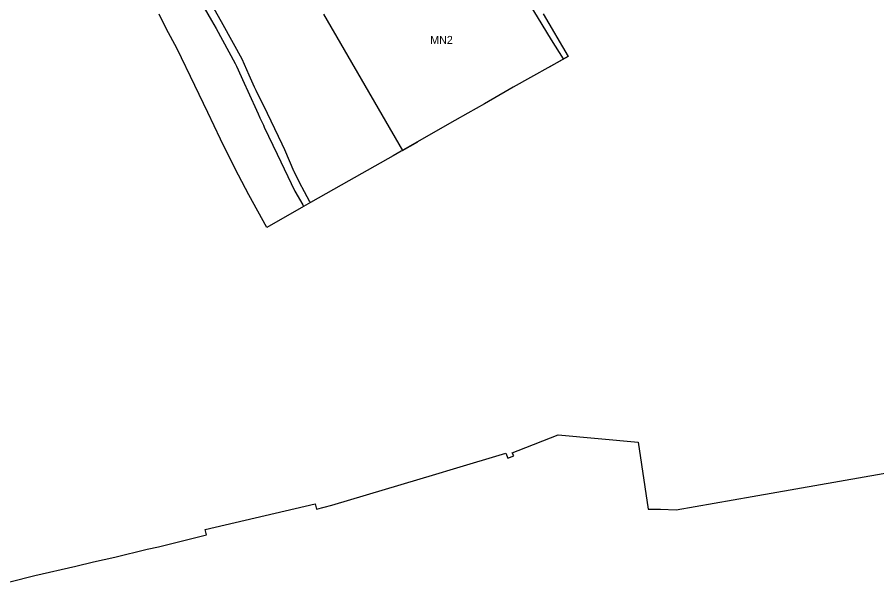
# Model space of a CAD drawing. Extents: x 7435758 to 7439981, y 5550649 to 5554049.
# Drawn here: x 7437513 to 7438071, y 5550874 to 5551241 of the extents above; entities that cross this region are included whole.
import ezdxf

# ---------------------------------------------------------------- set-up
doc = ezdxf.new("R2010")
doc.units = 0
for name, color, linetype in [('#Ruszcza', 7, 'Continuous'), ('linie_rozgraniczające', 7, 'Continuous'), ('linie_zabudowy_nieprzekraczalne', 7, 'Continuous'), ('oznaczenia_przeznaczen', 7, 'Continuous')]:
    doc.layers.add(name, color=color, linetype=linetype)

msp = doc.modelspace()

# ---------------------------------------------------------------- linework, layer by layer
at = {"layer": '#Ruszcza'}
for points in [[(7437854.67, 5551243.25), (7437871.03, 5551215.66), (7437835.33, 5551195.56), (7437832.76, 5551194.1), (7437816.62, 5551184.92), (7437805.84, 5551178.79), (7437797.36, 5551173.97), (7437781.8, 5551165.08), (7437762.51, 5551154.06), (7437757.35, 5551151.11), (7437728.49, 5551134.92), (7437703.62, 5551120.79), (7437699.13, 5551118.22), (7437675.21, 5551104.53), (7437663.51, 5551125.67), (7437656.96, 5551138.55), (7437649.87, 5551152.2), (7437645.25, 5551161.79), (7437636.88, 5551179.09), (7437628.45, 5551196.8), (7437617.02, 5551220.55), (7437609.91, 5551233.78), (7437605.33, 5551243.14)], [(7437508.31, 5550874.47), (7437524.48, 5550878.48), (7437551.28, 5550884.61), (7437562.64, 5550887.41), (7437576.65, 5550890.57), (7437597.53, 5550895.76), (7437604.87, 5550897.1), (7437619.64, 5550900.82), (7437636.09, 5550904.97), (7437635.19, 5550908.51), (7437706.77, 5550925.06), (7437707.57, 5550921.74), (7437717.56, 5550924.19), (7437785.08, 5550944.4), (7437796.47, 5550947.82), (7437830.56, 5550958.02), (7437831.89, 5550954.85), (7437835.66, 5550956.31), (7437834.56, 5550958.16), (7437838.51, 5550959.77), (7437864.51, 5550969.99), (7437916.46, 5550965.07), (7437922.95, 5550921.62), (7437930.91, 5550921.66), (7437941.14, 5550921.25), (7437990.62, 5550929.87), (7438103.91, 5550949.67)]]:
    msp.add_lwpolyline(points, dxfattribs=at)
at = {"layer": 'linie_rozgraniczające'}
for p, q in [((7437629.59, 5551255.8), (7437639.26, 5551239)), ((7437646.85, 5551236.19), (7437634.54, 5551258.52)), ((7437639.26, 5551239), (7437642.32, 5551233.68)), ((7437712.09, 5551243.15), (7437763.36, 5551154.58)), ((7437642.32, 5551233.68), (7437654.7, 5551211.03)), ((7437659.21, 5551213.76), (7437646.85, 5551236.19)), ((7437654.7, 5551211.03), (7437655.52, 5551209.24)), ((7437663.84, 5551203.45), (7437659.21, 5551213.76)), ((7437859.25, 5551209.03), (7437871, 5551215.7)), ((7437655.52, 5551209.24), (7437660.55, 5551198.16)), ((7437667.37, 5551195.62), (7437663.84, 5551203.45)), ((7437660.55, 5551198.16), (7437662.89, 5551193.01)), ((7437668.4, 5551193.49), (7437667.37, 5551195.62)), ((7437662.89, 5551193.01), (7437669.55, 5551178.39)), ((7437675.67, 5551178.51), (7437668.4, 5551193.49)), ((7437669.55, 5551178.39), (7437670.78, 5551175.69)), ((7437685.29, 5551158.53), (7437675.67, 5551178.51)), ((7437670.78, 5551175.69), (7437673.05, 5551170.95)), ((7437673.05, 5551170.95), (7437673.64, 5551169.71)), ((7437673.64, 5551169.71), (7437682.03, 5551152.21)), ((7437763.36, 5551154.58), (7437773.28, 5551160.21)), ((7437686.94, 5551154.85), (7437685.29, 5551158.53)), ((7437693.08, 5551140.58), (7437686.94, 5551154.85)), ((7437763.36, 5551154.58), (7437763.37, 5551154.55)), ((7437682.03, 5551152.21), (7437693.39, 5551128.22)), ((7437693.18, 5551140.38), (7437693.08, 5551140.58)), ((7437697.99, 5551130.67), (7437693.18, 5551140.38)), ((7437693.39, 5551128.22), (7437698.59, 5551119.16)), ((7437698.13, 5551130.43), (7437697.99, 5551130.67)), ((7437703.01, 5551121.53), (7437698.13, 5551130.43)), ((7437703.62, 5551120.79), (7437703.01, 5551121.53)), ((7437698.59, 5551119.16), (7437699.13, 5551118.22))]:
    msp.add_line(p, q, dxfattribs=at)
msp.add_lwpolyline([(7437854.67, 5551243.25), (7437871.03, 5551215.66), (7437835.33, 5551195.56), (7437832.76, 5551194.1), (7437816.62, 5551184.92), (7437805.84, 5551178.79), (7437797.36, 5551173.97), (7437781.8, 5551165.08), (7437762.51, 5551154.06), (7437757.35, 5551151.11), (7437728.49, 5551134.92), (7437703.62, 5551120.79), (7437699.13, 5551118.22), (7437675.21, 5551104.53), (7437663.51, 5551125.67), (7437656.96, 5551138.55), (7437649.87, 5551152.2), (7437645.25, 5551161.79), (7437636.88, 5551179.09), (7437628.45, 5551196.8), (7437617.02, 5551220.55), (7437609.91, 5551233.78), (7437605.33, 5551243.14)], dxfattribs=at)
at = {"layer": 'linie_zabudowy_nieprzekraczalne'}
msp.add_lwpolyline([(7437868.08, 5551214), (7437860.28, 5551226.39), (7437860.24, 5551226.45), (7437825.19, 5551284.1), (7437825.13, 5551284.2), (7437785.07, 5551353.65), (7437753.35, 5551406.01), (7437753.34, 5551406.04), (7437746.65, 5551417.27), (7437742.73, 5551423.43)], dxfattribs=at)

# ---------------------------------------------------------------- texts
at = {"layer": 'oznaczenia_przeznaczen'}
msp.add_text('MN2', height=5.2, dxfattribs=at).set_placement((7437781.4, 5551223.71))

doc.saveas('drawing.dxf')
